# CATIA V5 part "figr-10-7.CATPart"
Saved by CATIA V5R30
Part number: Part1
Bounding box of the stored display mesh (mm): x -9.616 to 10, y -9.533 to 9.835, z 0 to 10
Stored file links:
  D:\PROJECTS\CATIA V56R 2020\Resources\Parts File\c10_catia_v5_6r2020_prt\figr-10-7.CATPart
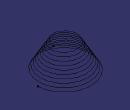
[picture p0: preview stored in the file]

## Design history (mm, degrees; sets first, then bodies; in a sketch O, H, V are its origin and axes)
Set1
  Helix1: Direction {line stored without definition}, RefPoint {point type Coord, X 10, Y 0, Z 0}, Pitch 1, Height 10, TaperAngle 30
Body1 (main body)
